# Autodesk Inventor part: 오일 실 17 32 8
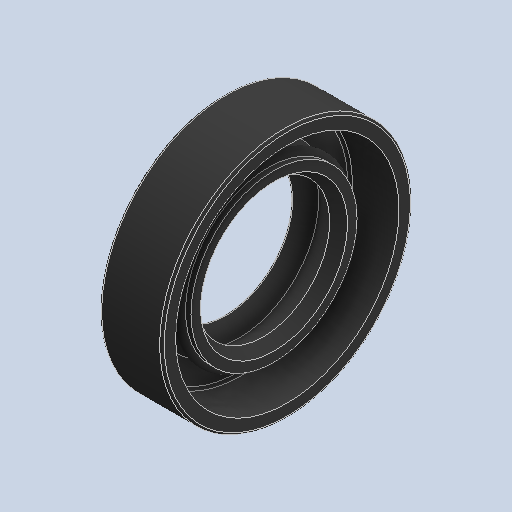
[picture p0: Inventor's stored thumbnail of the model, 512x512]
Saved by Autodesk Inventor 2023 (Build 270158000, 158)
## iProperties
Created: 2025-04
Part Number: 오일 실 17 32 8
Material: 고무
Description: 오일-실
Document SubType Name: Modeling
Designer: user
Density: 0.93 g/cm^3
Appearance: 기본값
Author: jhkim
Revision Number: 1
Sending System: Autodesk Inventor 2026
Preprocessor: ST-DEVELOPER v20.1
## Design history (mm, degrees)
feature "Solid1"
node "솔리드1"
